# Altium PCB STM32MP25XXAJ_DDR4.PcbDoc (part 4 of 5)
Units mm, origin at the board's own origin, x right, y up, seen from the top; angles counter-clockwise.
Board outline 172 x 137 mm, 4 copper layers (Top Layer, Signal Layer 1, Signal Layer 2, Bottom Layer), stack 1.614 mm thick; 226 components, 313 nets, 1113 pads, 850 vias.
Unrouted connection lines stored in the file: 13.
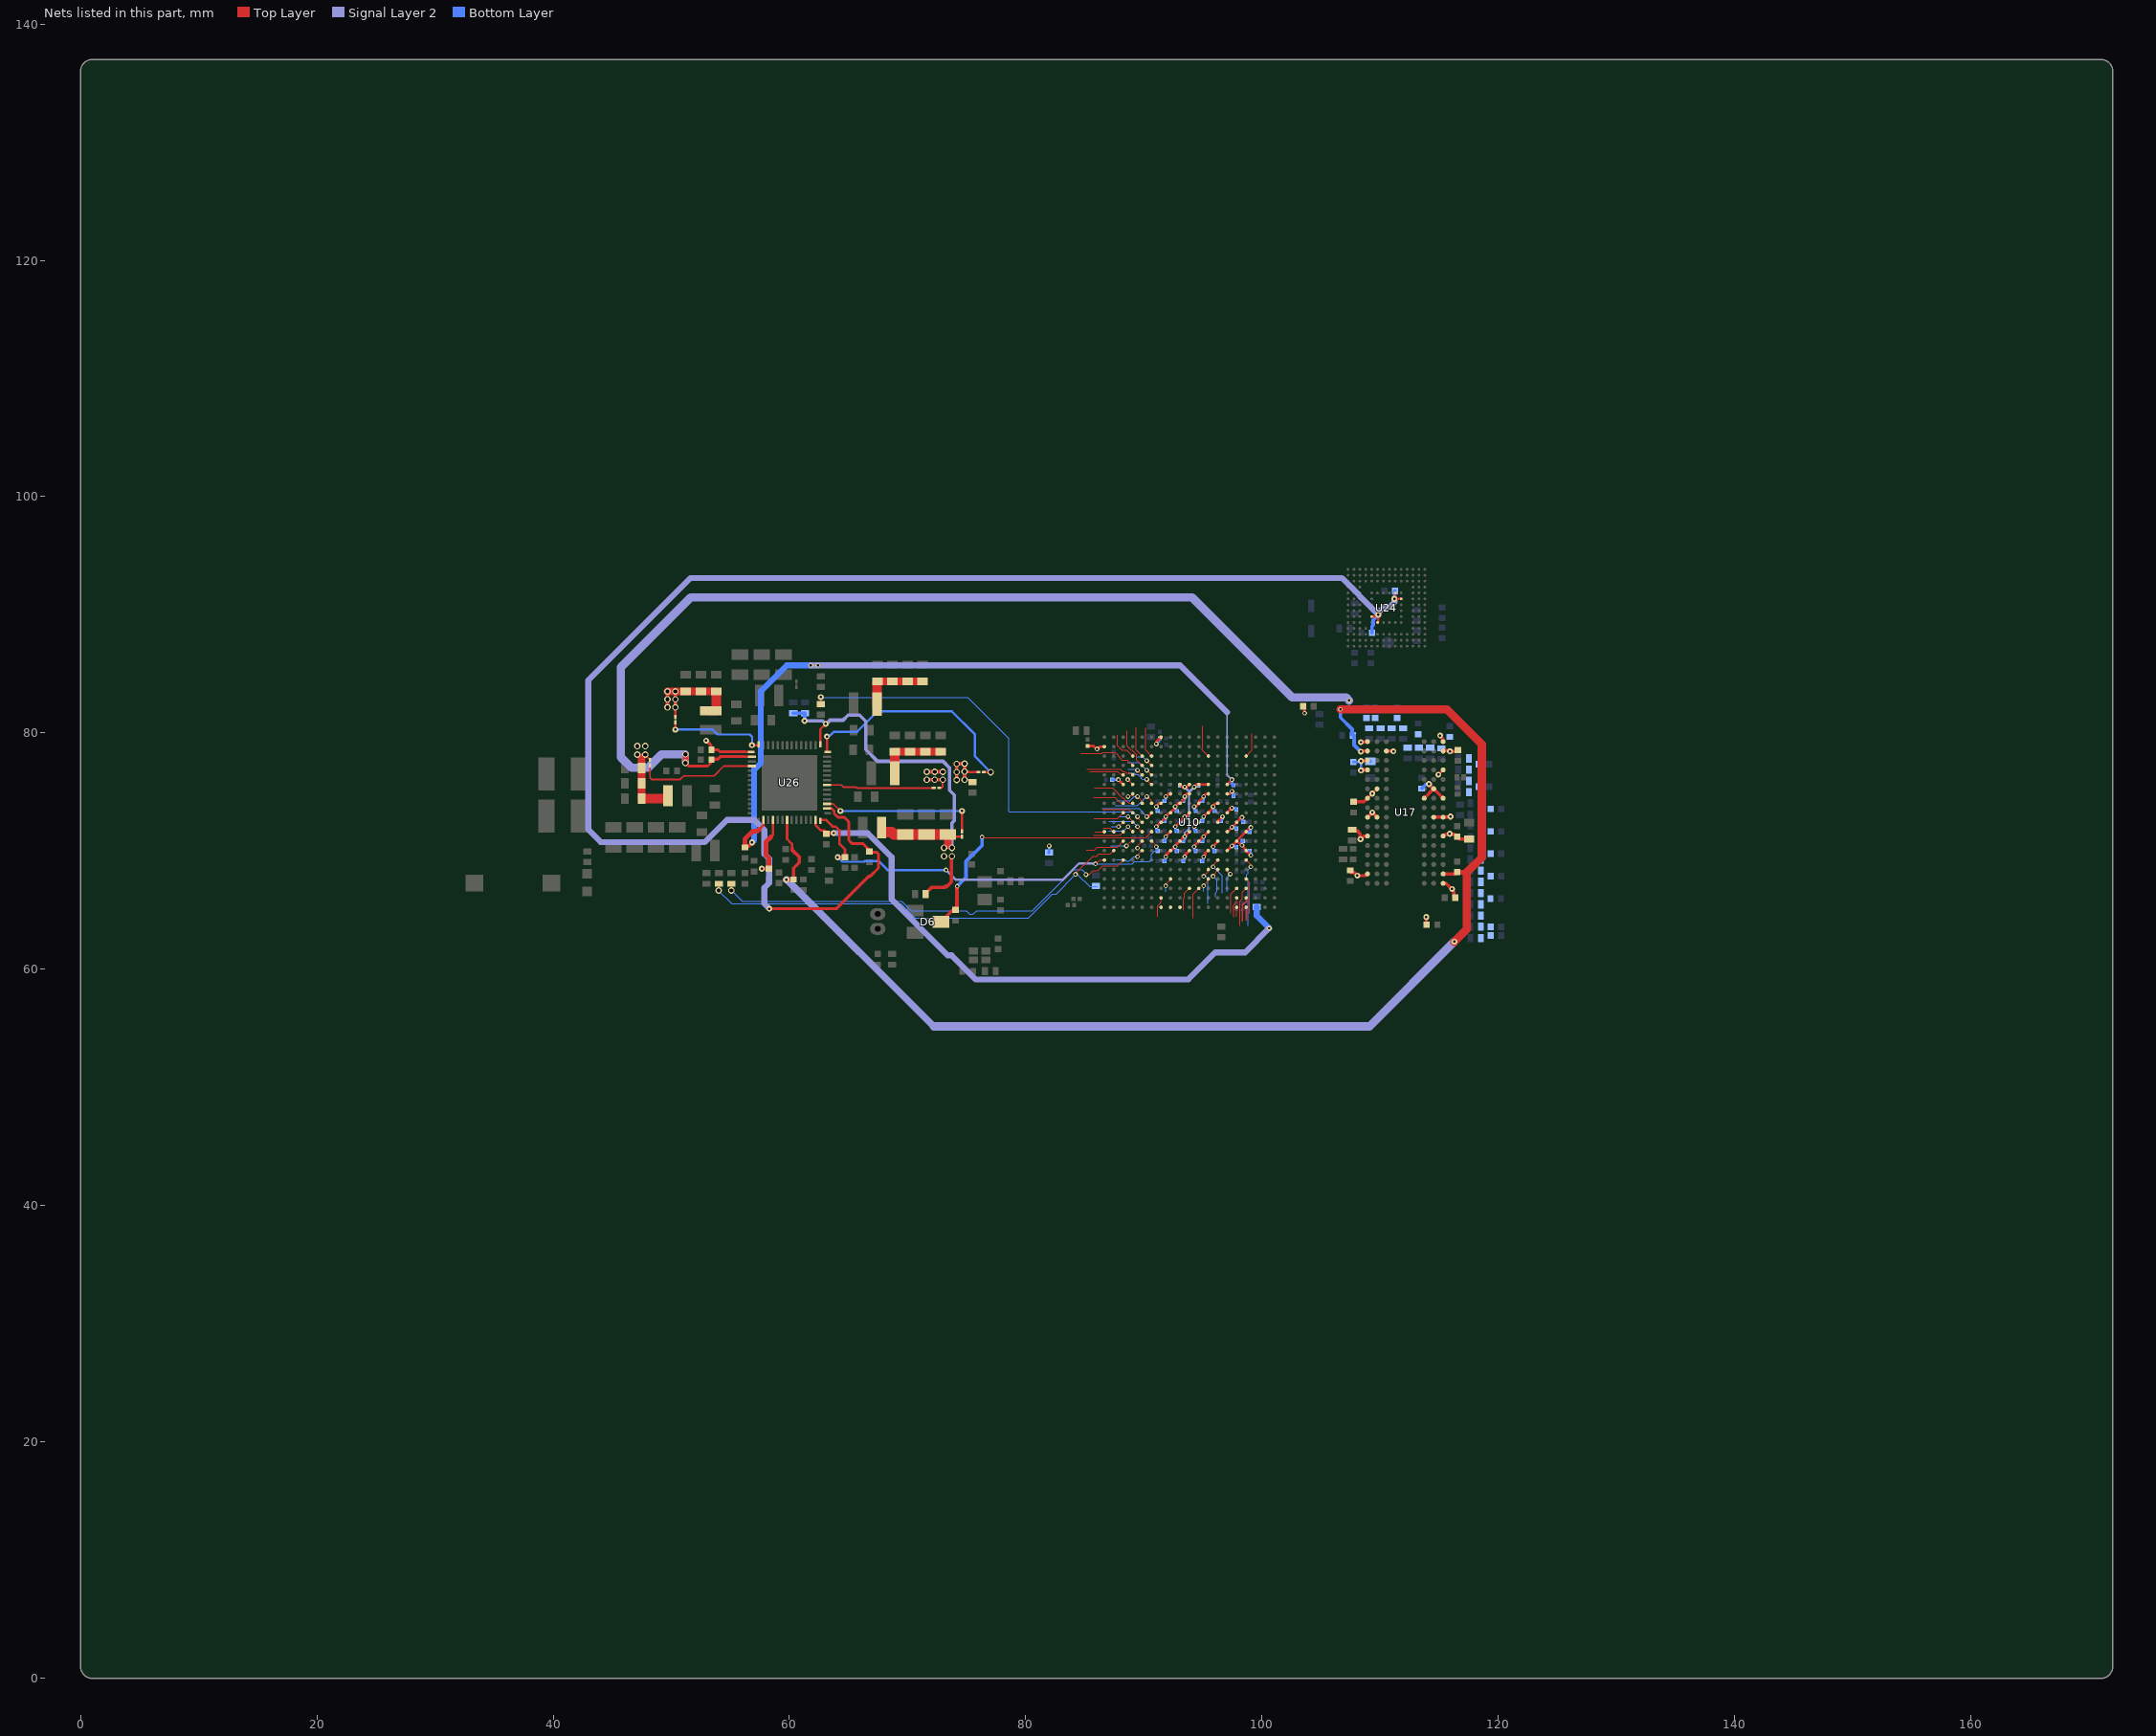
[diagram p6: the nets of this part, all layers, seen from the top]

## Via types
v1: diameter 0.55, hole 0.35, Top Layer to Bottom Layer, 344 vias
v2: diameter 0.5, hole 0.2, Top Layer to Bottom Layer, 250 vias
v3: diameter 0.4, hole 0.2, Top Layer to Bottom Layer, tented both sides, 180 vias
v4: diameter 0.4, hole 0.2, Top Layer to Bottom Layer, 76 vias

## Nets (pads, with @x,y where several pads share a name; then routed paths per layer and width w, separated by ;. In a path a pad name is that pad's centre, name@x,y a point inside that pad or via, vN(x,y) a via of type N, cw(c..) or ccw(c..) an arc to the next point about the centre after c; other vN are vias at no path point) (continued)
PG5: U10.H3 | length 2.7
  Top Layer w0.09: 85.717,74.539 87.552,74.539 88.034,74.057 88.243,74.057 U10.H3@88.25,74.05
PG6: U10.J3 | length 2.7
  Top Layer w0.09: 85.781,72.75 87.75,72.75 U10.J3@88.25,73.25
PG7: U10.F6 | length 2.4
  Top Layer w0.09: v3@90.239,75.981 90.276,75.981 90.608,75.65 U10.F6@90.645,75.65
  Bottom Layer w0.1: 88.684,76.617 89.188,76.617 89.305,76.5 89.52,76.5 89.8,76.22 89.8,76.134 89.859,76.075 v3(90.25,76.075)
PG8: U10.D4 | length 4.9
  Top Layer w0.1: 84.637,78.268 86.443,78.268 86.526,78.35 87.574,78.35 87.75,78.174 87.75,78.16 87.921,77.989 87.921,77.948 88.143,77.726 88.574,77.726 U10.D4@89.05,77.25
PG9: U10.E4 | length 4.1
  Top Layer w0.1: 85.171,76.95 88.024,76.95 88.224,76.75 88.374,76.75 88.524,76.6 88.9,76.6 U10.E4@89.05,76.45
PG10: U10.E5 | length 1.4
  Top Layer w0.09: v4(89.45,76.85) U10.E5@89.845,76.455
  Bottom Layer w0.09: 88.661,76.922 89.242,76.922 89.255,76.909 89.391,76.909 v4(89.45,76.85)
PG11: U10.E6 | length 2.5
  Top Layer w0.09: v3@90.245,76.85 U10.E6@90.645,76.45
  Bottom Layer w0.09: 88.6,77.5 89.6,77.5 v3(90.25,76.85)
PG12: U10.G4 | length 0.5
  Top Layer w0.1: v4(88.65,74.625) 88.825,74.625 U10.G4@89.05,74.85
PG13: U10.H5 | length 2.7
  Top Layer w0.1: v3(89.45,74.625) 89.825,74.249 89.825,74.075 U10.H5@89.85,74.05
  Bottom Layer w0.1: 87.67,74.275 88.832,74.275 89.168,74.612 89.437,74.612 v3(89.45,74.625)
PG14: U10.E3 | length 2.9
  Top Layer w0.1: 85.427,76.75 87.782,76.75 88.054,76.478 88.222,76.478 U10.E3@88.25,76.45
PG15: U10.C6 | length 2.6
  Top Layer w0.1: 90.15,79.774 90.15,78.726 90.149,78.551 U10.C6@90.65,78.05 ; 90.149,79.775 90.149,80.411
PH2: U10.P13 | length 3.2
  Top Layer w0.09: v3@95.845,68.773 95.845,68.809 96.245,69.209 U10.P13@96.245,69.25
  Bottom Layer w0.09: v3(95.85,68.675) 96.623,67.9 96.623,66.462
PH3: U10.T12 | length 1.2
  Top Layer w0.09: v3@95.05,67.079 95.424,67.453 95.424,67.629 U10.T12@95.445,67.65
  Bottom Layer w0.09: 95.05,66.595 v3(95.05,67.075)
PH4: U10.R13 | length 2.7
  Top Layer w0.09: v3(95.85,67.875) 95.85,67.949 96.089,68.188 96.089,68.282 U10.R13@96.25,68.443
  Bottom Layer w0.09: v3@95.854,67.875 95.854,67.871 96.195,67.53 96.195,66.6 96.045,66.449 96.045,66.12
PH5: U10.R14 | length 2.1
  Top Layer w0.1: U10.R14@97.05,68.45 97.05,68.308 v3(97.3,68.058)
  Bottom Layer w0.1: 97.04,66.575 97.04,67.798 v3(97.3,68.058)
PH6: U10.R12 | length 3.4
  Top Layer w0.09: v3(95.05,67.875) 95.41,68.235 95.41,68.41 U10.R12@95.45,68.45
  Bottom Layer w0.09: v3@95.05,67.97 95.124,67.97 95.43,67.665 95.43,67.082 95.429,67.081 95.429,65.552
PH7: U10.U10 | length 2
  Top Layer w0.09: 93.365,65.05 93.365,65.97 93.445,66.05 93.445,66.45 U10.U10@93.845,66.85
PH8: U10.U11 | length 2.7
  Top Layer w0.09: 94.152,64.354 94.152,66.358 U10.U11@94.645,66.85
PH9: U10.T8 | length 1.1
  Top Layer w0.09: v3@91.893,67.187 91.893,67.24 92.245,67.591 U10.T8@92.245,67.65
  Bottom Layer w0.09: 91.85,66.571 v3(91.85,67.075)
PH10: U10.W9
PH11: U10.W8
PH12: U10.V7 | length 1.7
  Top Layer w0.09: 91.15,64.445 91.15,65.372 91.445,65.667 U10.V7@91.445,66.05
PH13: U10.W7
PI0: U10.D6 | length 1.6
  Top Layer w0.1: v3@90.245,77.65 U10.D6@90.645,77.25
  Bottom Layer w0.1: 89.354,78.006 89.894,78.006 v3(90.25,77.65)
PI1: U10.F4 | length 0.6
  Top Layer w0.1: v4(88.632,76.05) 89.057,75.625 U10.F4@89.075,75.625
PI2: U10.J6 | length 4.6
  Top Layer w0.22: v3@90.259,72.838 90.259,72.848 90.645,73.234 U10.J6@90.645,73.25
  Bottom Layer w0.09: 86.463,73.597 89.578,73.597 v3(90.25,72.925)
PI3: U10.H4 | length 3.8
  Top Layer w0.09: 85.8,75.35 87.357,75.35 87.562,75.145 87.572,75.145 87.85,74.867 87.85,74.833 88.178,74.505 88.282,74.505 88.507,74.28 88.513,74.28 88.743,74.05 U10.H4@89.05,74.05
PI4: U10.H6 | length 3.8
  Top Layer w0.09: v3(90.25,74.625) 90.28,74.625 90.641,74.264 90.641,74.059 U10.H6@90.65,74.05
  Bottom Layer w0.09: 87.551,73.85 89.475,73.85 v3(90.25,74.625)
PI5: U10.D5 | length 3.5
  Top Layer w0.1: 88.554,80.166 88.554,78.936 88.75,78.74 88.75,78.726 88.923,78.553 88.957,78.553 89.16,78.35 89.174,78.35 89.39,78.134 89.39,77.71 U10.D5@89.85,77.25
PI6: U10.C5 | length 2.6
  Top Layer w0.1: 89.354,80.457 89.354,78.546 U10.C5@89.85,78.05
PI7: U10.C4 | length 2.5
  Top Layer w0.1: 87.756,79.813 87.756,78.933 87.95,78.74 87.95,78.726 88.116,78.56 88.54,78.56 U10.C4@89.05,78.05
PI8: U10.N5 | length 2.5
  Top Layer w0.09: v3@89.445,69.65 U10.N5@89.845,70.05
  Bottom Layer w0.09: 87.666,69.285 88.397,69.285 88.502,69.18 88.788,69.18 89.133,69.525 v3(89.45,69.525)
PI9: U10.J4 | length 2.6
  Top Layer w0.1: 86.526,73.55 88.746,73.55 89.046,73.25 U10.J4@89.05,73.25
PI10: U10.C12 | length 2.8
  Top Layer w0.1: 94.95,80.573 94.95,78.726 94.925,78.701 94.925,78.575 U10.C12@95.45,78.05
PI11: U10.C16 | length 2.1
  Top Layer w0.09: U10.C16@98.65,78.05 99.15,78.55 99.15,79.947
PMIC_WAKEUPn: R46.1 U10.K5 | length 35.7
  Top Layer w0.1: v3@89.445,72.85 U10.K5@89.845,72.45
  Top Layer w0.15: R46.1@62.65,82.448 v2(62.65,83.033)
  Bottom Layer w0.1: v2@62.703,83.022 75.078,83.022 78.559,79.541 78.559,73.388 78.617,73.33 89.045,73.33 v3(89.45,72.925)
PWR_CPU_ON: R60.1 R272.2 U10.N2 | length 39.6
  Top Layer w0.1: v1@54.014,66.64 54.014,67.229 R60.1@54.03,67.245 ; v4(84.214,68.036) 84.214,68.097 85.696,69.578 86.004,69.578 86.186,69.76 87.16,69.76 U10.N2@87.45,70.05
  Bottom Layer w0.1: v1(54.009,66.67) 55.107,65.572 69.42,65.572 70.634,64.358 78.204,64.358 80.233,64.358 82.263,66.387 82.587,66.387 84.214,68.014 v4(84.214,68.036) 84.38,68.036 85.416,67 R272.2@86,67
PWR_ON: R2.1 U10.P3 | length 36.9
  Top Layer w0.1: v1@55.08,66.64 R2.1@55.08,67.245 ; v4(85.1,68.025) 85.117,68.042 85.378,68.042 85.678,68.342 86.117,68.342 86.525,68.75 87.75,68.75 U10.P3@88.25,69.25
  Bottom Layer w0.1: v1(55.075,66.67) 55.119,66.67 56.017,65.772 69.502,65.772 70.317,64.957 74.948,64.957 75.255,64.65 75.545,64.65 75.853,64.957 80.55,64.957 84.018,68.425 84.775,68.425 v4@85.125,68.075
PZ0: U10.L5 | length 3.1
  Top Layer w0.1: v3@89.445,71.95 89.495,71.95 89.795,71.65 U10.L5@89.845,71.65
  Bottom Layer w0.1: 87.046,72.503 89.022,72.503 v3(89.45,72.075)
PZ1: U10.M3 | length 3.4
  Top Layer w0.09: 85.131,70.113 85.829,70.113 86.069,70.354 87.754,70.354 U10.M3@88.25,70.85
PZ2: U10.L3 | length 2.7
  Top Layer w0.09: 85.725,71.346 87.946,71.346 U10.L3@88.25,71.65
PZ3: U10.M5 | length 0.8
  Top Layer w0.1: v4(89.45,70.256) 89.507,70.314 89.507,70.507 U10.M5@89.85,70.85
PZ4: U10.L4 | length 2.3
  Top Layer w0.1: v3@88.648,72.031 88.659,72.031 89.039,71.65 U10.L4@89.045,71.65
  Bottom Layer w0.1: 87.041,71.714 88.289,71.714 v3(88.65,72.075)
PZ5: U10.M4 | length 2.1
  Top Layer w0.1: v3(88.525,70.45) 88.887,70.812 89.006,70.812 U10.M4@89.045,70.85
  Bottom Layer w0.1: 87.179,70.35 87.279,70.45 v3(88.525,70.45)
PZ6: U10.K4 | length 1.4
  Top Layer w0.1: v3(88.65,72.925) 89.05,72.525 U10.K4@89.05,72.45
  Bottom Layer w0.1: 87.9,72.925 v3(88.65,72.925)
PZ7: U10.L2 | length 1
  Top Layer w0.09: 86.54,71.975 87.125,71.975 U10.L2@87.45,71.65
PZ8: U10.K3 | length 1.2
  Top Layer w0.1: v4@87.851,72.06 87.86,72.06 U10.K3@88.25,72.45
  Bottom Layer w0.1: 87.223,72.075 v4(87.851,72.075)
PZ9: U10.L1 | length 0.8
  Top Layer w0.09: 85.875,71.65 U10.L1@86.65,71.65
UCPD1_CC1: U10.P16 | length 5.9
  Top Layer w0.09: U10.P16@98.65,69.25 99.05,68.85 v3(99.05,68.675)
  Bottom Layer w0.1: 98.8,63.713 98.8,67.63 98.7,67.73 98.7,68.02 98.8,68.12 98.8,68.425 v3(99.05,68.675)
UCPD1_CC2: U10.U15 | length 2.3
  Top Layer w0.1: 97.35,64.733 97.35,65.475 97.375,65.5 97.375,66.375 U10.U15@97.85,66.85
USB3DR_DM: U10.V16 | length 2.1
  Top Layer w0.11: 98.345,64.047 98.345,65.423 98.645,65.723 U10.V16@98.645,66.05
USB3DR_DP: U10.W16 | length 1.1
  Top Layer w0.11: 98.645,64.15 U10.W16@98.645,65.25
USB3DR_TXRTUNE: U10.T16 | length 3.1
  Top Layer w0.1: U10.T16@98.65,67.65 98.95,67.35 98.95,64.709
USBH_HS_DM: U10.V15 | length 1.8
  Top Layer w0.1: 97.594,64.438 97.594,65.082 97.55,65.126 97.55,65.392 97.85,65.692 U10.V15@97.85,66.05
USBH_HS_DP: U10.W15 | length 0.8
  Top Layer w0.09: 97.85,64.45 U10.W15@97.85,65.25
USBH_HS_TXRTUNE: U10.U16 | length 3.4
  Top Layer w0.1: 98.14,63.692 98.14,65.775 98.344,65.979 98.344,66.544 U10.U16@98.65,66.85
VBAT: C87.2 D6.3 U10.L6 | length 23.9
  Top Layer w0.09: v4(76.3,71.2) 76.344,71.156 90.156,71.156 U10.L6@90.65,71.65
  Top Layer w0.3: D6.3@73.2,64.375 72.85,64.025 D6.3@72.825,64.025 73.825,65.025 C87.2@74.05,65.025 ; C87.2@73.925,65.125 74.173,65.125 74.178,65.13 74.178,67.011 v3(74.197,67.03)
  Bottom Layer w0.3: v3(74.197,67.03) 74.952,67.785 74.952,69.133 76.3,70.481 v4(76.3,71.2)
VDD3V3_USB: C156.2 R197.1 U26.13 | length 50.4
  Top Layer w0.21: U26.13@62.2,72.63 62.2,72.2 62.663,71.737 62.918,71.737 62.92,71.735 62.99,71.735 63.125,71.6 C156.2@63.125,71.53
  Top Layer w0.3: C156.2@63.125,71.53 v2(63.735,71.53)
  Signal Layer 2 w0.5: v2(63.735,71.53) 66.62,71.53 68.65,69.5 68.65,65.93 73.395,61.185 73.717,61.185 75.752,59.15 93.752,59.15 96.035,61.433 98.571,61.433 v4(100.611,63.473)
  Bottom Layer w0.5: R197.1@99.55,65.275 99.55,64.534 v4@100.591,63.494
VDD_DDR: C39.2 C41.2 C70.2 C82.2 C104.2 C105.2 C106.2 C112.2 C172.2 C175.2 C176.2 C178.2 C179.2 C181.2 C195.2 C200.2 C201.2 C202.2 C218.2 C377.2 C383.2 C386.2 C389.1 L5.2 LNK8.2 R116.1 U10.G14 U10.J14 U10.K15 U10.L14 U10.L16 U10.M15 U10.N14 U10.N16 U17.A1 U17.A9 U17.B3 U17.B9 U17.C1 U17.D1 U17.D9 U17.F2 U17.F8 U17.G1 U17.G7 U17.G9 U17.J1 U17.J2 U17.J8 U17.J9 U17.L1 U17.L9 U17.R1 U17.T9 U26.43 | length 45.7
  Top Layer w0.15: v1(47.798,78.165) 48.2,77.763 LNK8.2@48.2,77.723
  Top Layer w0.2: U17.J1@108.927,72.873 U17.J1@108.95,72.873 ; U17.G1@108.969,74.515 109.312,74.858 v2@109.316,74.858 ; v2@109.325,74.85 109.325,74.871 U17.F2@109.727,75.273 ; v2@109.327,73.25 v2@109.327,73.273
  Top Layer w0.21: 56.275,78.4 U26.43@56.825,78.4
  Top Layer w0.22: U10.N14@97.05,70.05 v3(97.45,70.45) ; U10.L14@97.05,71.65 97.072,71.65 97.112,71.69 97.118,71.69 v3@97.45,72.022 ; U10.J14@97.05,73.25 97.3,73.5 v4@97.3,73.65 ; U10.G14@97.05,74.85 97.24,74.85 v3(97.45,75.06) ; v3(97.45,72.025) U10.K15@97.85,72.425 ; v3@97.456,70.45 U10.M15@97.85,70.844 ; U10.M15@97.85,70.85 97.872,70.85 97.912,70.81 97.94,70.81 v3@98.16,70.59 ; U10.K15@97.85,72.45 v3@98.25,72.85 ; U10.M15@97.875,70.875 U10.L16@98.65,71.65 98.966,71.966 99.016,71.966 v3(99.05,72) ; v3@98.161,70.59 98.251,70.5 v3(98.3,70.5) 98.3,70.461 98.635,70.126 98.635,70.065 U10.N16@98.65,70.05 v3(99.05,69.65) ; C70.2@103.475,82.25 103.575,82.15 v4@103.575,81.625 ; v2(114.925,76.475) U17.D9@115.325,76.875
  Top Layer w0.25: 53.195,79.125 53.199,79.125 53.345,78.979 53.345,78.685 C39.2@53.455,78.575 ; C39.2@53.505,78.575 53.975,78.575 54.15,78.4 56.275,78.4
  Top Layer w0.28: C104.2@107.397,68.308 107.512,68.193 107.788,68.193 108.053,67.928 108.744,67.928 108.889,68.073 U17.R1@108.927,68.073 ; R116.1@107.625,71.81 107.74,71.695 108.071,71.695 108.293,71.474 108.293,71.042 108.342,70.993 108.609,71.26 108.909,71.26 U17.L1@108.925,71.275 ; C105.2@107.737,74.178 108.632,74.178 U17.G1@108.969,74.515 ; v2@108.338,79.225 108.348,79.235 108.851,79.235 108.862,79.246 108.9,79.246 U17.A1@108.927,79.273 ; v2@109.327,73.273 U17.J2@109.727,72.873 ; U17.B3@110.525,78.475 110.537,78.463 v2@111.087,78.463 ; U17.G7@113.725,74.475 U17.F8@114.502,75.253 ; C82.2@113.902,63.768 v2@113.902,64.413 ; v2(114.125,75.675) 114.5,75.3 U17.F8@114.525,75.3 ; U17.J8@114.528,72.842 U17.J8@114.553,72.842 ; U17.J8@114.527,72.873 115.327,72.873 U17.J9@115.333,72.866 ; U17.F8@114.527,75.273 114.892,74.908 114.902,74.908 ; 114.963,74.837 115.327,74.473 U17.G9@115.325,74.475 ; v2@115.067,79.78 115.067,79.72 115.3,79.487 115.3,79.275 U17.A9@115.327,79.248 ; U17.T9@115.325,67.275 115.351,67.248 115.576,67.248 116.024,66.8 v2(116.075,66.8) 116.075,66.74 116.235,66.581 116.235,66.19 116.327,66.098 C106.2@116.347,66.098 ; U17.J9@115.325,72.875 115.9,72.875 v2(115.95,72.925) ; U17.L9@115.327,71.273 115.354,71.273 115.515,71.435 115.838,71.435 v2@115.877,71.473 ; U17.B9@115.327,78.473 115.353,78.5 115.831,78.5 115.914,78.417 v2@115.974,78.417 ; U17.A9@115.327,79.273 U17.A9@115.327,79.277 ; v2@115.877,71.419 v2@115.877,71.473 ; v2(115.9,78.45) 116.45,78.45 C178.2@116.6,78.6 ; C178.2@116.575,78.55 C178.2@116.6,78.55 ; C112.2@117.547,71.028 116.732,71.028 116.542,71.218 116.492,71.218 116.279,71.431 115.919,71.431 v2@115.877,71.473
  Top Layer w0.3: v2@52.944,79.376 53.195,79.125 ; v2@108.377,76.873 U17.D1@108.927,76.873 ; v2@108.377,77.673 U17.C1@108.927,77.673 ; U17.J1@108.95,72.873 v2@109.327,73.25
  Top Layer w0.64: C202.2@47.475,74.45 C41.2@47.475,75.75 C200.2@47.475,77.05 ; 47.475,77.495 47.475,77.925
  Top Layer w0.8: C202.2@47.7,74.45 L5.2@49.475,74.45
  Bottom Layer w0.22: v4(97.45,73.65) 97.7,73.65 C201.2@97.825,73.525 ; v3(97.45,70.45) 97.7,70.45 C386.2@97.825,70.325 ; v3(97.45,72.025) 97.7,72.025 C377.2@97.8,71.925 ; v3(97.45,75.06) 97.575,74.935 97.575,74.675 C176.2@97.575,74.65 ; v3@98.25,70.5 98.25,70.75 C389.1@98.375,70.875 ; v3(98.3,72.85) 98.3,72.575 C175.2@98.4,72.475 ; C195.2@98.925,70.025 99.05,69.9 v3(99.05,69.65) ; C383.2@98.925,71.625 99.05,71.75 v3(99.05,72) ; C218.2@107.725,77.55 108.325,77.55 v2@108.375,77.6 ; v2@108.4,76.8 v2(108.375,76.825) v2@108.375,77.6 ; C172.2@109.175,77.6 109.15,77.625 v2@108.4,77.625 ; v2@108.375,77.6 v2@108.4,77.625 ; v2@108.375,77.6 v2(108.375,77.625) v2@108.4,77.625
  Bottom Layer w0.28: C179.2@113.5,75.3 113.875,75.675 v2(114.125,75.675) v2@114.15,75.675
  other v1: 47.123,78.165 47.123,78.89 47.798,78.89
  other v2: 113.895,64.42 108.06,67.93 108.335,71.015 115.875,71.475 109.325,73.275 109.325,74.875 111.11,78.45 108.365,79.225 52.95,79.348 115.065,79.782
  other v4: 103.6,81.675
VDD_DDR_FB: LNK8.1 U26.46 | length 10.2
  Top Layer w0.15: LNK8.1@48.2,77.273 48.2,76.19 48.317,76.073 50.767,76.073 51.067,76.373 51.737,76.373 51.739,76.375 53.627,76.375 54.452,77.2 U26.46@56.83,77.2
VDD_EMMC: C177.2 C180.2 C190.1 U24.E6 U24.F5 U24.J10 U24.K9 U26.16 | length 133.5
  Top Layer w0.18: U24.E6@109.275,89.85 109.58,89.85 109.73,90 v2(109.825,90) ; U24.F5@109.775,89.35 109.775,89.358 109.825,89.408 v2@109.825,89.85 ; v2@111.2,91.25 v2@111.275,91.325 ; U24.J10@111.275,91.85 111.275,91.42 111.267,91.412 111.267,91.333 v2@111.275,91.325 ; U24.K9@111.775,91.35 111.395,91.35 111.362,91.317 111.283,91.317 v2@111.275,91.325
  Top Layer w0.21: U26.16@63.17,73.6 63.6,73.6 63.788,73.412 63.788,73.188 63.934,73.041
  Top Layer w0.25: v2(58.3,65.125) 63.96,65.125 66.7,67.865 66.822,67.865 67.535,68.578 67.535,69.764 67.389,69.91 66.805,69.91 C190.1@66.75,69.965 ; 63.932,73.038 64.098,72.872 64.628,72.872 65.025,72.475 65.025,70.925 65.3,70.65 66.195,70.65 C190.1@66.75,70.095
  Signal Layer 2 w0.5: v2@58.31,65.125 57.882,65.553 57.882,66.908 58.275,67.301 58.275,69.369 57.882,69.762 57.882,71.786 57.019,72.649 54.713,72.649 52.837,70.773 44.034,70.773 42.968,71.839 42.968,84.457 51.626,93.115 106.736,93.115 v2@109.688,90.163 ; v2@109.835,90 109.845,90.01 109.845,90.196 110.269,90.62 110.485,90.62 110.747,90.62 111.21,91.083 v2@111.21,91.25
  Bottom Layer w0.3: C180.2@109.3,88.475 109.3,89.049 109.4,89.149 109.4,89.575 v2(109.825,90) ; v2@111.2,91.25 111.225,91.275 111.225,92 C177.2@111.25,92.025
  other v2: 111.2,91.35
VDD_SDCARD: C142.1 U26.4 | length 5.1
  Top Layer w0.21: 58.425,71.2 58.6,71.375 U26.4@58.6,72.63
  Top Layer w0.3: v2(57.665,68.51) C142.1@58.275,68.51
  Top Layer w0.4: C142.1@58.275,68.51 58.275,69.393 58.01,69.658 58.01,70.785 58.425,71.2
VDDA1V8_AON: C189.2 C393.2 U10.M6 U10.P1 U26.14 | length 36.2
  Top Layer w0.1: v4@85.9,68.875 86.275,69.25 U10.P1@86.65,69.25 ; U10.M6@90.65,70.85 91.025,70.475 v3@91.025,70.375
  Top Layer w0.21: U26.14@62.6,72.63 63.11,72.63 63.648,72.092 63.887,72.092 64.245,71.734 64.245,70.602 64.7,70.147 C189.2@64.7,69.49
  Top Layer w0.3: v2(64.09,69.49) C189.2@64.7,69.49
  Signal Layer 2 w0.2: v3(73.253,68.406) 73.259,68.406 74.065,67.6 83.15,67.6 84.519,68.97 85.689,68.97 85.741,68.918 85.868,68.918 v4@85.906,68.88
  Bottom Layer w0.1: v4@85.906,68.88 85.953,68.927 89.027,68.927 89.205,69.106 90.456,69.106 90.64,69.29 90.64,69.739 90.897,69.995 C393.2@91.104,69.995
  Bottom Layer w0.12: v3(91.05,70.375) v3@91.104,70.321 ; C393.2@91.104,70.071 C393.2@91.175,70
  Bottom Layer w0.2: v2(64.09,69.49) 64.48,69.1 66.321,69.1 66.392,69.171 67.535,69.171 68.3,68.406 v3(73.253,68.406) ; C393.2@91.104,70.071 v3@91.104,70.321
  other v4: 85.9,68.925
VDDCORE: C22.2 C23.2 C24.2 C161.2 C164.1 C166.2 C167.2 C169.2 C173.1 C183.2 C353.2 C355.2 C372.2 C378.2 C390.2 L2.2 LNK2.2 R199.1 U10.A7 U10.B1 U10.F3 U10.G8 U10.G10 U10.H7 U10.H9 U10.J8 U10.J10 U10.K7 U10.K9 | length 24.8
  Top Layer w0.09: v3@91.89,74.475 v3@91.89,74.485
  Top Layer w0.2: C22.2@71.275,84.375 C22.2@71.323,84.423 ; v1@74.87,76.685 LNK2.2@75.98,76.685
  Top Layer w0.22: C353.2@85.225,78.9 85.73,78.9 85.998,78.632 86.088,78.632 86.291,78.835 86.635,78.835 U10.B1@86.65,78.85 ; v4(87.825,76.05) 87.825,76.038 88.044,75.82 88.08,75.82 U10.F3@88.25,75.65 ; v3(91.05,72.075) 91.063,72.075 91.438,72.45 U10.K7@91.445,72.45 ; v3(91.05,73.775) 91.05,73.822 91.252,74.025 91.425,74.025 U10.H7@91.45,74.05 ; v4@91.05,79.056 91.084,79.091 91.084,79.284 U10.A7@91.45,79.65 ; U10.K7@91.458,72.45 91.816,72.807 91.816,72.891 v3(91.85,72.925) 91.85,72.953 92.107,73.21 92.21,73.21 U10.J8@92.25,73.25 92.65,73.65 v3(92.65,73.775) v3@92.65,73.779 ; v3(91.85,74.625) 91.884,74.625 92.094,74.835 92.246,74.835 U10.G8@92.25,74.839 ; v3(92.65,72.075) 92.675,72.075 U10.K9@93.05,72.45 93.05,72.472 93.09,72.512 93.09,72.545 v3@93.45,72.905 ; v3@92.65,73.8 v3@92.65,73.779 ; v3(93.45,72.925) 93.484,72.959 93.56,72.959 U10.J10@93.85,73.25 ; U10.G10@93.845,74.85 93.624,74.85 93.45,74.676 v3(93.45,74.625) 93.45,74.45 U10.H9@93.05,74.05 93.035,74.035 92.906,74.035 v3@92.65,73.779
  Top Layer w0.3: v1@74.151,77.404 v1(74.826,77.404) v1(74.826,76.729) ; v1(74.156,76.024) v1(74.156,76.699) v1(74.156,77.374) ; v1(74.826,76.054) v1(74.826,76.729) ; v1@74.87,76.685 v1(74.826,76.729)
  Top Layer w0.64: C183.2@67.45,84.375 C24.2@68.725,84.375 C23.2@70,84.375 C22.2@71.275,84.375
  Top Layer w0.8: L2.2@67.415,82.2 L2.2@67.415,82.45 C183.2@67.415,84.173
  Bottom Layer w0.2: C161.2@87.325,76.05 v4(87.825,76.05) ; v4(91.05,79.075) 91.275,79.3 91.275,79.475 C355.2@91.35,79.55
  Bottom Layer w0.22: v3(91.05,72.075) 91.05,71.825 C378.2@91.175,71.7 ; v3(91.05,73.775) 91.05,73.55 C173.1@91.175,73.425 ; C169.2@91.725,72.55 91.85,72.675 v3(91.85,72.925) ; C166.2@91.725,74.275 91.85,74.4 v3(91.85,74.625) ; v3(92.65,72.075) 92.65,71.825 C372.2@92.775,71.7 ; v3(92.65,73.775) 92.65,73.525 C167.2@92.775,73.4 ; C164.1@93.325,72.55 93.45,72.675 v3(93.45,72.925) ; C390.2@93.35,74.275 93.45,74.375 v3(93.45,74.625)
  other v4: 86.025,78.65
VDDCORE_FB: LNK2.1 U26.28 | length 19.9
  Top Layer w0.2: U26.28@63.17,78.4 v2(63.17,79.7) ; LNK2.1@76.444,76.687 v1@77.031,76.685
  Bottom Layer w0.2: v2(63.17,79.7) 63.227,79.757 63.401,79.757 63.754,80.111 65.734,80.111 67.457,81.833 73.744,81.833 75.675,79.902 75.675,78.041 v1(77.033,76.683)
VDDCPU: C26.2 C27.2 C28.2 C159.2 C163.2 C168.2 C174.1 C360.1 L3.2 LNK4.1 U10.G12 U10.H11 U10.H13 U10.J12 U10.K13 | length 16.3
  Top Layer w0.2: LNK4.1@50.35,81.35 v1(50.35,82.173)
  Top Layer w0.22: v3(94.25,73.775) 94.284,73.809 94.437,73.809 94.61,73.982 94.61,73.988 94.65,74.028 94.65,74.2 v3@95.075,74.625 ; v3@95.05,72.93 95.355,73.235 95.435,73.235 U10.J12@95.45,73.25 95.875,73.675 v3@95.875,73.697 ; v3(95.05,74.625) 95.05,74.64 95.249,74.839 95.434,74.839 U10.G12@95.445,74.85 ; v3(95.85,73.775) 95.85,73.816 96.055,74.022 96.216,74.022 U10.H13@96.245,74.05 ; U10.K13@96.25,72.45 96.265,72.465 96.265,72.523 v3@96.65,72.907
  Top Layer w0.3: v1(49.675,82.173) v1(49.675,82.848) v1(49.675,83.523) v1(50.35,83.523) v1(50.35,82.848) v1(50.35,82.173)
  Top Layer w0.64: v1(49.675,83.523) 49.675,83.525 C27.2@51.2,83.525 C28.2@52.5,83.525 C26.2@53.8,83.525
  Top Layer w0.8: L3.2@53.35,81.875 53.8,81.875 53.8,83.173
  Bottom Layer w0.22: v3(94.25,73.775) 94.25,73.525 C159.2@94.375,73.4 ; C168.2@94.925,72.525 95.05,72.65 v3(95.05,72.925) ; C360.1@94.925,74.25 95.05,74.375 v3(95.05,74.625) ; v3(95.85,73.775) 95.85,73.525 C174.1@95.975,73.4 ; C163.2@96.5,72.55 96.65,72.7 v3(96.65,72.925)
VDDCPU_FB: LNK4.2 U26.42 | length 8.6
  Top Layer w0.2: v2(50.35,80.29) LNK4.2@50.35,80.9 ; v2(56.825,78.975) U26.42@57.395,78.975
  Bottom Layer w0.2: v2@50.37,80.287 53.499,80.287 53.914,79.872 56.643,79.872 56.845,79.67 v2@56.845,78.972
VDDGPU: C34.2 C35.2 C36.2 C37.2 C191.1 C381.2 C382.2 C388.2 C402.2 L4.2 LNK7.2 U10.K11 U10.L12 U10.M11 U10.M13 U10.N12 | length 14.9
  Top Layer w0.15: LNK7.2@72.675,75.35 72.682,75.358 72.885,75.358 72.973,75.445 v1(72.973,76.038)
  Top Layer w0.2: C35.2@73.05,78.393 C35.2@73.098,78.345
  Top Layer w0.22: v3(94.25,70.375) 94.25,70.45 U10.M11@94.65,70.85 95.025,71.225 v3(95.05,71.225) ; v3@94.27,72.075 U10.K11@94.645,72.45 ; v3(95.05,69.525) 95.2,69.675 95.2,69.844 95.406,70.05 U10.N12@95.445,70.05 ; v3(95.85,70.375) 95.85,70.412 96.245,70.807 U10.M13@96.245,70.85
  Top Layer w0.24: v3@95.05,71.25 U10.L12@95.45,71.65
  Top Layer w0.3: v1(71.623,76.038) v1(72.298,76.038) v1(72.973,76.038) ; v1(71.623,76.713) v1(72.298,76.713) v1(72.973,76.713) ; v3(95.05,71.225) v3@95.05,71.25
  Top Layer w0.64: C37.2@68.9,78.4 C36.2@70.2,78.4 C34.2@71.5,78.4 C35.2@72.8,78.4
  Top Layer w0.8: L4.2@68.925,76.6 68.925,78.073
  Bottom Layer w0.22: v3(94.25,70.375) 94.25,70.125 C381.2@94.375,70 ; v3(94.25,72.075) 94.25,71.825 C388.2@94.375,71.7 C388.2@94.4,71.675 ; C402.2@94.925,69.15 95.05,69.275 v3(95.05,69.525) ; v3(95.85,70.375) 95.85,70.125 C191.1@95.975,70
  Bottom Layer w0.24: C382.2@94.925,70.85 95.05,70.975 v3(95.05,71.225)
  Bottom Layer w0.3: v3@94.2,70.4 v3@94.225,70.4
VDDGPU_FB: LNK7.1 U26.21 | length 9.3
  Top Layer w0.15: U26.21@63.05,75.6 64.383,75.6 64.56,75.423 65.64,75.423 65.713,75.35 LNK7.1@72.225,75.35
VDDIO: C19.2 C143.2 C186.2 C187.2 C192.2 C342.2 C380.2 C387.1 C399.1 C400.2 L6.2 LNK11.2 R27.2 R67.2 R260.2 R261.2 U10.F9 U10.F10 U10.F11 U10.F12 U10.L8 U10.L10 U10.M9 U10.N8 U10.N10 U26.29 | length 54.1
  Top Layer w0.09: U10.L10@93.85,71.65 U10.L10@93.874,71.626
  Top Layer w0.2: U26.29@62.6,79.045 62.6,80.298 v2(63.075,80.773) ; C186.2@73.4,71.4 73.585,71.215 LNK11.2@74.6,71.215 ; v3@93.45,71.227 93.45,71.239 93.838,71.626 U10.L10@93.874,71.626
  Top Layer w0.22: v3@91.844,71.227 91.827,71.244 91.833,71.244 92.239,71.65 U10.L8@92.245,71.65 ; v3(91.85,69.525) 91.85,69.65 U10.N8@92.25,70.05 92.325,70.05 v3(92.65,70.375) 92.698,70.423 92.698,70.498 U10.M9@93.05,70.85 93.425,71.225 v3(93.45,71.225) ; U10.F9@93.05,75.65 93.275,75.425 v3(93.45,75.425) 93.625,75.425 U10.F10@93.837,75.638 ; v3(93.45,69.525) 93.45,69.65 U10.N10@93.85,70.05 ; U10.F10@93.825,75.65 U10.F10@93.837,75.638 ; U10.F10@93.85,75.625 U10.F10@93.837,75.638 ; U10.F10@93.85,75.65 U10.F10@93.837,75.638 ; v3(94.25,75.425) 94.475,75.65 U10.F11@94.647,75.65 ; U10.F11@94.647,75.647 U10.F11@94.647,75.65 ; U10.F11@94.65,75.65 U10.F11@94.647,75.65 ; U10.F12@95.445,75.65 U10.F11@94.647,75.65
  Top Layer w0.3: R67.2@71.525,66.375 71.525,66.44 72.01,66.925 73.125,66.925 73.23,67.03 73.339,67.03 73.712,67.402 73.712,69.52 v1(73.752,69.56) ; v1(73.077,69.56) v1@73.125,69.512
  Top Layer w0.64: 73.4,70.525 C186.2@73.4,70.955
  Top Layer w0.9: L6.2@67.85,71.6 68.65,71.6 68.85,71.4 C187.2@69.8,71.4 C19.2@71.6,71.4 C186.2@73.4,71.4
  Signal Layer 2 w0.15: v3(93.45,71.225) 93.45,71.545 93.826,71.921 93.826,75.049 93.825,75.05
  Signal Layer 2 w0.22: v3(93.45,75.425) 93.825,75.05 93.875,75.05 v3(94.25,75.425)
  Signal Layer 2 w0.3: v2(61.284,81.027) 62.799,81.027 63.05,80.776 v2@63.075,80.776 ; v2(63.075,80.773) 63.129,80.773 63.44,81.084 64.543,81.084 64.973,81.513 65.931,81.513 66.455,80.989 66.455,78.601 67.456,77.6 72.999,77.6 73.551,77.048 73.551,75.156 73.951,74.756 73.951,72.573 73.752,72.375 v1(73.752,70.285)
  Bottom Layer w0.15: C143.2@93.05,75.55 93.125,75.475 v3@93.425,75.475
  Bottom Layer w0.22: R27.2@81.95,69.85 81.975,69.875 R27.2@81.975,69.9 v4(81.975,70.45) ; C399.1@91.725,69.15 91.85,69.275 v3(91.85,69.525) ; C387.1@91.725,70.825 91.85,70.95 v3(91.85,71.225) ; v3(92.65,70.375) 92.65,70.125 C192.2@92.775,70 ; C400.2@93.325,69.15 93.45,69.275 v3(93.45,69.525) ; C380.2@93.325,70.85 93.45,70.975 v3(93.45,71.225) ; v3(94.25,75.425) 94.375,75.55 C342.2@94.625,75.55
  Bottom Layer w0.3: R260.2@60.33,81.68 R261.2@61.305,81.68 61.294,81.669 61.294,81.038 v2(61.284,81.027)
  other v1: 73.077,70.285
VDDIO_FB: LNK11.1 U26.17 | length 13.4
  Top Layer w0.15: U26.17@63.17,74 63.7,74 64.303,73.397 v2(64.315,73.397)
  Top Layer w0.2: LNK11.1@74.6,71.665 v2(74.6,73.4)
  Bottom Layer w0.15: v2(64.315,73.397) v2@74.597,73.397
VDDIO_SDCARD: C217.1 C357.2 U10.F14 U26.2 | length 66.6
  Top Layer w0.21: 57.459,71.873 57.8,72.214 U26.2@57.8,72.63
  Top Layer w0.22: U10.F14@97.05,75.65 v3(97.45,76.05)
  Top Layer w0.3: C217.1@56.225,70.38 56.27,70.425 56.559,70.425 56.835,70.701 v2(56.835,70.737)
  Top Layer w0.4: C217.1@56.225,70.32 56.225,70.38 56.225,71.015 56.899,71.69 57.275,71.69 57.459,71.873
  Signal Layer 2 w0.15: 97.035,81.754 97.035,76.465 v3(97.45,76.05)
  Signal Layer 2 w0.5: v4(61.82,85.726) v4(62.398,85.726) 93.063,85.726 97.035,81.754
  Bottom Layer w0.3: v3(97.45,76.05) 97.45,75.675 C357.2@97.55,75.575
  Bottom Layer w0.5: v2(56.835,70.737) 57.009,70.911 57.009,76.91 57.581,77.482 57.581,81.596 57.575,81.601 57.575,82.099 57.581,82.104 57.581,83.542 59.765,85.726 v4(61.82,85.726) v4(62.398,85.726)
VPP_DDR: C91.1 C252.2 C255.2 U17.B1 U17.R9 U26.7 | length 108.2
  Top Layer w0.21: U26.7@59.8,72.63 59.8,71.025 60.215,70.61 60.215,70.253
  Top Layer w0.3: v2(59.74,67.58) C91.1@60.35,67.58 ; 60.215,70.253 60.215,70.118 60.835,69.498 60.835,69.035 60.35,68.55 C91.1@60.35,67.73 ; v2@108.367,78.473 U17.B1@108.927,78.473 ; U17.R9@115.327,68.073 C252.2@116.347,68.073
  Top Layer w0.4: C252.2@116.517,68.218 117.317,68.218
  Top Layer w0.7: v4(106.625,82) 115.637,82 118.594,79.044 118.594,69.47 117.367,68.243 ; v2@116.271,62.342 117.317,63.388 117.317,68.218
  Signal Layer 2 w0.6: v2(59.74,67.58) 59.793,67.58 72.203,55.171
  Signal Layer 2 w0.7: 72.203,55.171 109.095,55.171 v2(116.275,62.35)
  Bottom Layer w0.3: v4(106.625,82) 106.625,81.318 107.623,80.32 107.623,79.852 C255.2@107.675,79.8 ; C255.2@107.788,79.8 107.788,78.98 108.193,78.575 108.211,78.575 108.311,78.475 v2@108.365,78.475
  other v2: 108.365,78.425
VTT_DDR: C40.2 C144.2 C145.2 C146.2 C160.2 C226.2 C239.2 C254.2 C256.2 C257.2 C258.2 C259.2 C261.2 C265.2 C266.2 R252.2 R253.2 R254.2 R255.2 R256.2 R257.2 R258.2 R259.2 R263.2 R264.2 R265.2 R266.2 R268.2 R271.2 R273.2 R275.2 R276.2 R277.2 R278.2 R279.2 R280.2 R281.2 R282.2 R283.2 R284.2 U26.44 | length 89.3
  Top Layer w0.21: 56.275,78 U26.44@56.83,78
  Top Layer w0.25: v1(51.2,78.198) v1@51.202,78.196 ; v1@51.225,77.473 51.202,77.473 51.475,77.2 53.075,77.2 53.32,77.445 53.32,77.635 53.435,77.75 C40.2@53.505,77.75 ; C40.2@53.51,77.635 53.665,77.79 53.94,77.79 54.15,78 56.275,78
  Top Layer w0.5: v1@51.202,77.473 v1@51.202,78.196
  Signal Layer 2 w0.6: v1@51.2,77.5 v1@51.2,78.223
  Signal Layer 2 w0.7: v1@51.15,78.2 49.178,78.2 48.038,77.06 46.623,77.06 45.738,77.946 45.738,85.572 51.638,91.472 94.083,91.472 102.552,83.003 107.122,83.003 v4(107.375,82.75)
  other v1: 51.2,77.473
pads on no net: U10.G17 U10.K17 U10.N17 U10.P17 U17.P9 U17.T7 U24.A1 U24.A2 U24.A7 U24.A8 U24.A9 U24.A10 U24.A11 U24.A12 U24.A13 U24.A14 U24.B1 U24.B7 U24.B8 U24.B9 U24.B10 U24.B11 U24.B12 U24.B13 U24.B14 U24.C1 U24.C3 U24.C5 U24.C7 U24.C8 U24.C9 U24.C10 U24.C11 U24.C12 U24.C13 U24.C14 U24.D1 U24.D2 U24.D3 U24.D4 U24.D12 U24.D13 U24.D14 U24.E1 U24.E2 U24.E3 U24.E5 U24.E8 U24.E9 U24.E10 U24.E12 U24.E13 U24.E14 U24.F1 U24.F2 U24.F3 U24.F10 U24.F12 U24.F13 U24.F14 U24.G1 U24.G2 U24.G3 U24.G10 U24.G12 U24.G13 U24.G14 U24.H1 U24.H2 U24.H3 U24.H12 U24.H13 U24.H14 U24.J1 U24.J2 U24.J3 U24.J12 U24.J13 U24.J14 U24.K1 U24.K2 U24.K3 U24.K6 U24.K7 U24.K10 U24.K12 U24.K13 U24.K14 U24.L1 U24.L2 U24.L3 U24.L12 U24.L13 U24.L14 U24.M1 U24.M2 U24.M3 U24.M7 U24.M8 U24.M9 U24.M10 U24.M11 U24.M12 U24.M13 U24.M14 U24.N1 U24.N3 U24.N6 U24.N7 U24.N8 U24.N9 U24.N10 U24.N11 U24.N12 U24.N13 U24.N14 U24.P1 U24.P2 U24.P7 U24.P8 U24.P9 U24.P10 U24.P11 U24.P12 U24.P13 U24.P14

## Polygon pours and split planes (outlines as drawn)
GND on Bottom Layer "GND_L04" (solid, pour order 155): 0.225,137.075 172,137.075 172,-0.225 0.025,-0.225
VTT_DDR on Bottom Layer "VTT_DDR_L04_P154" (solid, pour order 154): 107.575,80.775 107.025,81.325 107.025,83.075 107.05,83.1 108.3,83.1 108.45,82.95 108.45,81.8 108.625,81.625 111.85,81.625 112.975,80.5 117.7,80.5 118.875,79.325 118.875,75.25 119.9,74.225 119.9,62.275 118.052,62.275 118.099,74.351 117.825,74.625 117.05,74.625 117.05,78.125 116.85,78.325 112.65,78.325 112.325,78.65 112.325,79.875 108.475,79.875
VDD_DDR on Signal Layer 2 "VDD_DDR" (solid, remove dead copper, pour order 144): 49.219,81.75 52.65,81.75 53.225,81.175 53.225,78.95 52.725,78.45 49.211,78.464 48.216,77.468 46.918,77.468 46.246,78.14 46.246,85.378 50.853,89.985 96.09,89.985 106.3,79.775 117.05,79.775 117.05,74.525 118.05,74.525 118.05,62.275 105.572,62.28 98.912,68.94 98.476,68.94 97.25,70.174 97.25,81.325 94.48,84.095 49.539,84.095 49.219,83.775
GND on Signal Layer 2 "GND_L03" (solid, remove dead copper, pour order 152): -0.042,136.898 172,136.898 172,-0.102 -0.042,-0.102
1V8 on Signal Layer 2 "1V8" (solid, pour order 151): 60.675,96.6 60.675,93.472 101.693,93.472 101.748,83.8 116.35,83.8 117.725,85.175 117.725,96.6
VDDIO on Signal Layer 2 "VDDIO_L03" (solid, remove dead copper, pour order 145): 93.617,71.95 93.613,71.945 93.613,69.59 91.403,69.59 89.378,67.564 74.378,67.564 72.553,69.389 72.553,71.646 73.744,72.838 90.259,72.838 91.146,71.95
VDDCPU on Signal Layer 2 "VDDCPU" (solid, remove dead copper, pour order 143): 94.074,72.5 94.074,74.752 93.212,75.614 93.212,76.951 91.618,78.545 81.766,78.735 66.455,78.545 66.455,80.62 66.505,80.67 66.175,81 60.143,81 60.055,80.912 59.116,81.85 49.319,81.85 49.219,81.75 49.219,83.775 50.843,85.4 59.717,85.4 60.603,84.513 60.603,84.5 93.85,84.5 96.931,81.419 96.931,72.5
5V_STLK on Signal Layer 2 "5V_STLK_L03" (solid, pour order 150): 43.375,82.635 68.35,82.635 68.35,66.229 43.411,66.229
3V3 on Signal Layer 2 "3V3_L03" (solid, remove dead copper, pour order 146): 58,61.394 57.939,61.394 37.983,61.394 35.711,61.394 35.711,67.822 35.711,84.011 44.436,84.011 44.436,73.55 45.447,72.539 58,72.539
VDDCORE on Signal Layer 2 "VDDCORE" (solid, remove dead copper, pour order 142): 85.2,78.6 85.925,79.325 91.1,79.325 91.55,78.875 91.542,78.592 93.08,77.054 93.08,75.225 93.657,74.608 93.657,72.016 93.508,71.868 90.93,71.868 89.779,73.018 73.707,73.018 73.707,78.6
VDDGPU on Signal Layer 2 "VDDGPU" (solid, remove dead copper, pour order 127): 97.148,69.67 97.148,72.308 94.868,72.308 93.988,72.308 93.666,71.986 93.666,70.788 93.666,69.512 91.192,69.512 89.374,67.715 74.374,67.715 72.549,69.54 72.549,71.782 73.63,72.863 73.63,77.29 68.13,77.29 66.599,75.759 66.599,73.523 68.4,71.766 68.4,66.459 74.813,60.175 93.875,60.175 98.541,64.841 98.541,68.277 97.306,69.512
GND on Top Layer "GND_L01" (solid, pour order 153): 0.178,137.102 0.303,136.977 172,136.977 172,-0.323 0.103,-0.323
VDDCORE on Top Layer "I_SENS_VDDCORE_P" (solid, pour order 134): 72.507,84.74 75.389,81.858 75.389,75.631 75.394,75.626 73.94,75.626 73.395,76.171 73.395,80.872 73.022,81.245 71.375,81.245 67.015,81.245 67.005,84.74
3V3 on Top Layer "3V3" (solid, pour order 137): 44.387,68.548 44.562,68.373 50.91,68.373 52.212,69.675 52.212,70.523 44.588,70.523 44.387,70.323
5V_STLK on Top Layer "5V_STK" (solid, pour order 111): 54.01,75.62 54.667,75.62 54.85,75.803 54.85,75.463 54.367,74.98 54.01,74.98
VDDCPU on Top Layer "I_SENS_VDDCPU_P" (solid, pour order 133): 49.312,83.845 49.312,81.998 49.835,81.475 54.25,81.475 54.245,81.48 54.245,83.845
VDDGPU on Top Layer "I_SENS_VDDGPU_P" (solid, pour order 135): 73.103,75.6 73.245,75.742 73.245,78.72 68.525,78.72 68.525,75.6
VDDIO on Top Layer "VDDIO" (solid, pour order 136): 62.495,78.77 62.495,80.568 63.03,81.103 63.212,81.103 63.65,80.664 63.65,80.123 62.95,79.423 62.95,78.77
NetL6_1 on Top Layer "NetL6_1" (solid, pour order 138): 64.875,73.863 65.338,73.4 66.6,73.4 66.6,71.1 66.598,71.098 65.301,71.098 65.301,72.722 64.875,73.148
GND on Signal Layer 1 "GND_L02" (solid, remove dead copper, pour order 99): -1,138 172,138 172,-1 -1,-1

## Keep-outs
Keep-Out Layer:
  lines w0.1: 133.661,133.38 142.561,133.38 142.561,135.53 133.661,135.53 133.661,133.38

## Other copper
Top Layer:
  rectangle net VDD_DDR: 47.155,73.8 50.125,75.6
  region net 5V_STLK: 56.73,80.524 56.631,80.425 56.275,80.425 cw(c56.275,80.775) 55.925,80.775 55.925,80.825 55.2,80.825 ccw(c55.2,80.75) 55.125,80.75 55.125,80.4 ccw(c55.327,80.397) 55.325,80.195 57.95,80.195 58.35,79.8 58.612,79.8 57.891,80.521 57.625,80.525
  region net 5V_STLK: 65.105,79.78 64.93,79.672 ccw(c65.063,79.473) 64.894,79.642 64.853,79.601 ccw(c65.113,79.342) 64.746,79.342 64.746,79.326 ccw(c65.101,79.326) 64.85,79.075 64.85,77.539 64.849,77.538 64.847,77.551 64.376,77.08 63.77,77.08 63.77,77.345 64.006,77.345 64.48,77.819 64.48,80.347 64.808,80.67 65.825,80.67 65.825,79.78
  region net GND: 56.4,79.685 56.307,79.685 ccw(c56.307,79.584) 56.235,79.655 55.955,79.375 ccw(c56.026,79.303) 55.925,79.303 55.925,78.975 56.425,78.975 cw(c56.823,78.982) 56.815,79.38 57.075,79.375 ccw(c57.075,79.423) 57.109,79.389 57.205,79.485
  region net GND: 63.725,76 63.65,75.925 63.572,75.925 cw(c63.572,75.798) 63.662,75.888 63.688,75.862 ccw(c63.778,75.952) 63.778,75.825 64.447,75.825 cw(c64.447,75.698) 64.537,75.788 64.6,75.725 64.729,75.854 cw(c64.78,75.803) 64.78,75.875
  region net NetL1_1: 59.072,81.875 ccw(c58.769,81.883) 58.978,82.102 58.955,82.125 58.955,82.187 59.026,82.194 ccw(c59.025,82.194) 59.025,82.195 59.175,82.075
  pour cut-out: 99.35,78.975 101.875,81.5 114.425,81.5 114.45,81.525 117.1,78.875 117.1,68.1 112.575,63.575 100.1,63.575 98.875,64.8 98.875,65.35
  pour cut-out: 96.375,78.95 96.4,78.975 96.4,82.975 100.125,86.7 100.1,86.725 100.1,90.95 101.9,92.75 105.35,92.75 108.15,89.95 112.45,89.95 112.45,89.375 113.325,88.5 113.325,86.9 113,86.9 109.875,83.775 109.85,83.8 104.875,83.8 100.025,78.95
  pour cut-out: 85.9,80.025 101.175,80.025 101.175,64.825 85.75,64.825
  region net 5V_STLK: 65.695,78.175 65.695,77.32 65.625,77.25 65.5,77.375 64.9,77.375 65.055,77.53 65.055,78.175
  region net 5V_STLK: 65.625,77.25 65.05,76.675 64.375,76.675 64.375,76.85 64.9,77.375
  region net 5V_STLK: 54.375,72.9 54.216,72.9 54.189,72.874 54.148,72.842 54.102,72.815 54.054,72.795 54.003,72.782 53.951,72.775 53.925,72.774 53.425,72.774 53.399,72.775 53.347,72.782 53.296,72.795 53.248,72.815 53.202,72.842 53.161,72.874 53.15,72.45 53.15,71.945 52.875,71.945 52.875,71.305 53.33,71.305 54.099,72.074 54.099,72.184 54.103,72.227 54.113,72.27 54.129,72.31 54.152,72.346 54.18,72.379 54.538,72.737
  region net 5V_STLK: 51.575,71.948 52.225,71.948 52.225,71.305 51.92,71.305 51.825,71.4 51.575,71.4
  region net 5V_STLK: 54.75,75.62 54.75,75.4 54.33,74.98 52.65,74.98 52.65,75.525 52.9,75.525 52.995,75.62
  region net 5V_STLK: 65.575,73.875 65.575,74.125 64.675,75.025 65.425,75.025 65.747,74.703
  region net 5V_STLK: 65.575,73.85 65.477,73.948 65.477,74.625 66.12,74.625 66.12,73.895 66.075,73.85 66.075,73.6 65.575,73.6
  region net 5V_STLK: 58.675,81.85 58.77,81.755 58.77,81.45 58.13,81.45 58.13,81.805 58.175,81.85 58.175,82.1 58.675,82.1
  region net 5V_STLK: 58.925,79.725 58.9,79.725 58.13,80.495 58.13,80.825 58.77,80.825 58.77,80.605 58.9,80.475 58.9,79.925
  region net 5V_STLK: 65.675,81 65.825,80.85 65.825,80.6 65.025,80.6 65.025,80.85 65.175,81 65.175,81.25 65.675,81.25
  region net 5V_STLK: 65.625,79.35 65.775,79.2 65.775,78.95 64.975,78.95 64.975,79.2 65.125,79.35 65.125,79.6 65.625,79.6
  region net 5V_STLK: 54.75,81.3 54.795,81.345 55.15,81.345 55.15,80.65 54.9,80.65 54.75,80.8 54.5,80.8 54.5,81.3
  region net GND: 51.575,72.75 51.62,72.705 52.18,72.705 52.225,72.75 52.225,73.345 51.92,73.345 51.825,73.25 51.575,73.25
  region net GND: 50.525,72.798 50.675,72.648 50.675,72.398 49.8,72.398 49.8,72.823 50.025,73.048 50.525,73.048
  region net GND: 50.525,72.798 50.375,72.648 50.375,72.398 51.2,72.398 51.2,72.873 51.025,73.048 50.525,73.048
  region net GND: 72.3,73.298 72.3,74.651 70.9,74.651 70.9,73.298
  region net GND: 59.525,87.425 59.675,87.275 59.675,87.025 58.8,87.025 58.8,87.45 59.025,87.675 59.525,87.675
  region net GND: 59.525,87.425 59.375,87.275 59.375,87.025 60.2,87.025 60.2,87.5 60.025,87.675 59.525,87.675
  region net GND: 57.675,87.425 57.825,87.275 57.825,87.025 56.95,87.025 56.95,87.45 57.175,87.675 57.675,87.675
  region net GND: 57.675,87.425 57.525,87.275 57.525,87.025 58.35,87.025 58.35,87.5 58.175,87.675 57.675,87.675
  region net GND: 56.1,81.323 56.297,81.52 56.75,81.52 56.75,80.63 56.293,80.63 56.1,80.823
  region net GND: 45.125,72.798 44.975,72.648 44.975,72.398 45.8,72.398 45.8,72.873 45.625,73.048 45.125,73.048
  region net GND: 45.125,72.798 45.275,72.648 45.275,72.398 44.4,72.398 44.4,72.823 44.625,73.048 45.125,73.048
  region net GND: 46.925,72.798 46.775,72.648 46.775,72.398 47.6,72.398 47.6,72.873 47.425,73.048 46.925,73.048
  region net GND: 46.925,72.798 47.075,72.648 47.075,72.398 46.2,72.398 46.2,72.823 46.425,73.048 46.925,73.048
  region net GND: 45.1,74.7 45.295,74.895 46.075,74.895 46.075,74.005 45.295,74.005 45.1,74.2
  region net GND: 48.725,72.798 48.575,72.648 48.575,72.398 49.4,72.398 49.4,72.873 49.225,73.048 48.725,73.048
  region net GND: 48.725,72.798 48.875,72.648 48.875,72.398 48,72.398 48,72.823 48.225,73.048 48.725,73.048
  region net GND: 57.075,79.375 56.74,79.375 56.74,79.385
  region net GND: 63.421,78.656 63.52,78.656 63.549,78.653 63.578,78.644 63.604,78.63 63.627,78.612 63.645,78.589 63.67,78.555 63.67,78.23 63.77,78.23 63.77,78.93 63.421,78.93
  region net GND: 53.425,72.952 53.23,73.147 53.23,73.602 54.12,73.602 54.12,73.147 53.925,72.952
  region net GND: 64.33,76.125 64.78,76.125 64.78,75.825 64.655,75.7 64.48,75.875 64.33,75.875
  region net GND: 45.1,77.3 45.295,77.495 46.075,77.495 46.075,76.605 45.295,76.605 45.1,76.8
  region net GND: 45.1,76 45.295,76.195 46.075,76.195 46.075,75.305 45.295,75.305 45.1,75.5
  region net GND: 51.45,85.873 51.645,85.678 51.645,85.223 50.755,85.223 50.755,85.678 50.95,85.873
  region net GND: 52.75,85.873 52.945,85.678 52.945,85.223 52.055,85.223 52.055,85.678 52.25,85.873
  region net GND: 54.05,85.873 54.245,85.678 54.245,85.223 53.355,85.223 53.355,85.678 53.55,85.873
  region net GND: 55.775,83.373 55.97,83.178 55.97,82.723 55.08,82.723 55.08,83.178 55.275,83.373
  region net GND: 55.825,87.425 55.675,87.275 55.675,87.025 56.5,87.025 56.5,87.5 56.325,87.675 55.825,87.675
  region net GND: 55.825,87.425 55.975,87.275 55.975,87.025 55.1,87.025 55.1,87.45 55.325,87.675 55.825,87.675
  region net GND: 70.45,80.825 70.645,80.63 70.645,79.775 69.755,79.775 69.755,80.63 69.95,80.825
  region net GND: 69.15,80.825 69.345,80.63 69.345,79.775 68.455,79.775 68.455,80.63 68.65,80.825
  region net GND: 67.7,86.825 67.895,86.63 67.895,85.775 67.005,85.775 67.005,86.63 67.2,86.825
  region net GND: 74.1,73.298 74.1,74.651 72.7,74.651 72.7,73.298
  region net GND: 70.5,73.298 70.5,74.651 69.1,74.651 69.1,73.298
  region net GND: 73.05,80.825 73.245,80.63 73.245,79.775 72.355,79.775 72.355,80.63 72.55,80.825
  region net GND: 71.75,80.825 71.945,80.63 71.945,79.775 71.055,79.775 71.055,80.63 71.25,80.825
  region net GND: 68.975,86.825 69.17,86.63 69.17,85.775 68.28,85.775 68.28,86.63 68.475,86.825
  region net GND: 70.25,86.825 70.445,86.63 70.445,85.775 69.555,85.775 69.555,86.63 69.75,86.825
  region net GND: 71.525,86.825 71.72,86.63 71.72,85.775 70.83,85.775 70.83,86.63 71.025,86.825
  region net GND: 67.8,78.325 67.605,78.13 66.75,78.13 66.75,79.02 67.605,79.02 67.8,78.825
  region net GND: 67.825,79.975 67.63,79.78 66.775,79.78 66.775,80.67 67.63,80.67 67.825,80.475
  region net GND: 68.002,74.375 67.807,74.18 67.5,74.18 67.5,75.07 67.975,75.07 68.17,74.875 68.17,74.375
  region net VDD_DDR: 47.795,77.615 47.795,77.731 48.148,78.084 48.148,79.215 47.795,79.215 47.155,79.215 46.798,79.215 46.798,78.019 47.155,77.662 47.155,77.238 47.795,77.238
  region net VDDIO: 73.08,70.835 73.08,70.719 72.727,70.366 72.727,69.235 73.08,69.235 73.72,69.235 74.077,69.235 74.077,70.431 73.72,70.788 73.72,71.212 73.08,71.212
  pour cut-out: 74.825,62.125 78.033,62.125 78.26,62.125 78.785,61.6 78.785,59.714 78.283,59.211 74.825,59.211
  pour cut-out: 68.455,77.45 67.395,77.45 67.395,75.35 68.455,75.35
  pour cut-out: 74.1,71.925 69.13,71.925 69.13,72.575 74.1,72.575
  pour cut-out: 67.4,73.075 66.6,73.075 66.6,70.975 67.4,70.975
  pour cut-out: 67.355,72.875 69.13,72.875 69.13,71.6 67.8,71.6
  pour cut-out: 52.3,81.605 52.3,80.545 54.4,80.545 54.4,81.605
  pour cut-out: 66.945,83.25 65.885,83.25 65.885,81.15 66.945,81.15
  region net NetL1_1: 59.495,82.275 59.15,81.93 58.695,82.385 58.695,84.075 59.495,84.075
  pour cut-out: 58.655,84.225 57.935,84.225 57.935,82.125 58.655,82.125
  region net NetL2_1: 65.15,82.225 65.15,81.45 65.015,81.45 64.325,80.76 64.325,78 63.85,77.525 63.525,77.525 63.525,77.675 63.614,77.675 63.77,77.831 63.95,78.011 64.005,78.094 64.025,78.191 64.025,78.742 64.07,78.85 64.07,79.01 64.009,79.157 63.897,79.269 63.77,79.322 63.75,79.325 63.75,83.102 64.098,83.45 65.015,83.45 65.15,83.315 65.15,83.2
  region net NetL5_1: 50.925,75.948 51.15,76.173 52.525,76.173 52.525,74.323 52.002,73.8 51.725,73.8 50.925,73.8
  pour cut-out: 49.995,73.65 51.055,73.65 51.055,75.75 49.995,75.75
  region net NetL4_1: 66.025,77.6 66.025,75.6 66.934,75.6 66.934,77.6
  region net NetL7_1: 54.375,70.35 54.075,70.05 53.3,70.05 53.3,70.95 54.375,72.02
  region net NetL3_1: 54.075,78.975 52.888,80.162 53.988,80.162 54.075,80.075 57.68,80.075 57.92,79.835 56.29,79.835 56.267,79.833 56.248,79.829 56.22,79.82 56.201,79.813 56.175,79.799 56.158,79.788 56.135,79.769 55.841,79.474 55.822,79.452 55.811,79.435 55.802,79.419 55.79,79.39 55.786,79.378 55.781,79.362 55.777,79.342 55.776,79.327 55.774,79.313 55.774,78.975
  region net NetL3_1: 55.283,80.045 55.254,80.048 55.225,80.057 55.151,80.089 55.125,80.103 55.103,80.122 55.047,80.18 55.028,80.203 55.014,80.229 54.988,80.294 54.981,80.316 54.958,80.347 54.933,80.367 54.897,80.391 54.851,80.4 54.075,80.4 54.075,79.263
  pour cut-out: 53,72.6 51.05,72.6 51.05,72.025 53,72.025
  pour cut-out: 44.4,70.773 51.05,70.773 51.05,71.573 44.4,71.573
  pour cut-out: 53.44,71.1 52.38,71.1 52.38,69 53.44,69
  pour cut-out: 80.125,68.05 80.125,66.8 78.28,66.8 78.28,65.25 75.75,65.25 75.75,68.05
  pour cut-out: 106.875,94 107.125,94.25 114,94.25 114.175,94.075 114.175,87.1 114,86.925 107.15,86.925 106.875,87.2
  text "1" at 134.025,133.811 h2
Signal Layer 1:
  text "2" at 135.309,133.811 h2
Signal Layer 2:
  text "5" at 140.661,133.833 h2
Bottom Layer:
  pour cut-out: 97.15,76.525 97.225,76.6 97.225,81.725 99.45,83.95 101.95,83.95 102.575,83.325 102.575,79.025 100.025,76.475
  pour cut-out: 98.95,77.3 102.325,80.675 105.3,80.675 106.425,79.55 112.15,79.55 112.3,79.4 112.3,78.4 112.45,78.25 117.15,78.25 117.15,74.875 117.55,74.475 118.2,74.475 118.2,62.15 117.225,62.15 117.225,62.625 114.75,65.1 113.825,65.1 111.75,63.025 105.35,63.025 100.925,67.45 100.4,67.45 98.95,69.2
  text "6" at 142.16,133.822 h2

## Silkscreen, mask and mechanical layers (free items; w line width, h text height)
Top Overlay:
  text "J" at 47.231,116.442 h15
  text "VBAT" at 63.012,59.791 h1.2
Top Solder:
  region: 133.736,135.455 133.736,133.455 142.486,133.455 142.486,135.455
Bottom Solder:
  region: 133.736,135.455 133.736,133.455 142.486,133.455 142.486,135.455
M1-Board Shape:
  lines w0.1: 1,137 ccw(c1,136) 0,136 0,95 0,1 ccw(c1,1) 1,0 171,0 ccw(c171,1) 172,1 172,136 ccw(c171,136) 171,137 ; 1,137 1,137 ; 1,137 171,137 ; 171,137 171,137
M2-Board Dimensions:
  lines w0.1: 1,137 ccw(c1,136) 0,136 0,1 ccw(c1,1) 1,0 171,0 ccw(c171,1) 172,1 172,136 ccw(c171,136) 171,137 ; 1,137 1,137 ; 1,137 171,137 ; 171,137 171,137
